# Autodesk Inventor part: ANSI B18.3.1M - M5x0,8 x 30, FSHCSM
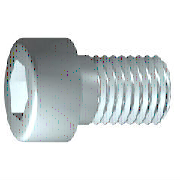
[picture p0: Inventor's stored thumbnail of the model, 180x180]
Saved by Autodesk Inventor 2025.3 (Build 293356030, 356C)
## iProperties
Created: 2024-01
Part Number: ANSI B18.3.1M - M5x0,8 x 30, FSHCSM
Material: Acciaio, Dolce
Description: Vite forgiata a testa incassata - Metrico
Document SubType Name: Modeling
Standard: ANSI B18.3.1M
Designer: R5800u
Standard Revision: 1979
Standards Organization: ANSI
Language: it-IT
Size Designation: M5x0,8 x 30
Categories: <MemberInstance><Categories><Category DisplayName="Elementi di fissaggio" InternalName="e4da775c-781d-43d5-af7c-5136215cf5a6" Mnemonic="FSTN"><Category DisplayN
Density: 7.85 g/cm^3
Appearance: Semilucidato
IsCustomPart: 0
Author: R5800u
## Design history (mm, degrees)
revolve "Corpo" stored, may be unused: angle "d10" = 90 deg
sketch "Schizzo2"
  geometry: L1 (0, -5.95)-(0, 5.95) reference; L2 (-5.95, 0)-(5.95, 0) reference; L3 (2.309, 0)-(1.155, -2); L4 (1.155, -2)-(-1.155, -2); L5 (-1.155, -2)-(-2.309, 0); L6 (-2.309, 0)-(-1.155, 2); L7 (-1.155, 2)-(1.155, 2); L8 (1.155, 2)-(2.309, 0); 2 further points
  constraints: 12 end point, 1 coincident, 1 horizontal alignment, 1 point on line, 12 other
extrude "Intaglio" join sketch "Schizzo2" stored distance "d11" = 10; taper "d12" = 0 deg
workplane "Work Plane1"
fillet "Fillet2" dims "d30" = 0.1 (= R)
body "Solid1"
fillet "Raccordo1" dims "d17" = 0.5 (= RR)
feature "Filettatura" dims "d13" = 29 (= GEL), "d14" = 0
chamfer "Smusso1" distance "d15" = 0.49076 (= -0.5 x SPD + 0.5 x GD); stored, may be unused: second distance "d16" = 0.49076 (= GUL), angle "d27" = 45 deg
sketch "Schizzo1"
  geometry: L1 (-1.167, 0)-(30, 0); L2 (30, 0)-(30, 2.5); L3 (30, 2.5)-(1, 2.5); L4 (1, 2.5)-(0.509, 2.5); L5 (0.509, 2.5)-(0, 2.5); L6 (0, 2.5)-(0, 4.25); L7 (0, 4.25)-(-5, 4.25); L8 (-5, 4.25)-(-5, 2.309); L9 (-5, 2.309)-(-2.5, 2.309); L10 (-2.5, 2.309)-(-1.167, 0); L11 (-12, 0)-(37, 0) reference; L12 (0, -0.85)-(0, 5.1) reference; L13 (1, 2.5)-(0, 2.5)
  constraints: 22 end point, 6 parallel, 2 collinear, 2 perpendicular, 1 horizontal, 1 point on line
  dimensions: "d1" = 29 distance from line of L3.end L2 (= GEL); "d2" = 0.49086 distance of L4.end L3.end (computed from GAL); "d3" = 5 distance between parallel lines of L8 L6 (= KOH); "d4" = 2.5 distance of L8.end L9.end (= INTI); "d5" = 60 deg angle of L10 L1; "d6" = 5 diameter of L3 L1 (= GD); "d7" = 5 diameter of L5 L1 (= BDM); "d8" = 4.6188 diameter of L9 L1 (= 1.1547 x SW); "d9" = 8.5 diameter of L7 L1 (= KOD); "d26" = 30 distance between parallel lines of L12 L2 (= NLG)
other parameters: "GD" = 5 (= NND) [user parameter; used in 2 equation terms], "NLG" = 30 [user parameter; used in 1 equation term], "GEL" = 29 [user parameter; used in 2 equation terms], "KOD" = 8.5 [user parameter; used in 1 equation term], "KOH" = 5 [user parameter; used in 1 equation term], "INTI" = 2.5 [user parameter; used in 1 equation term], "GAL" = 0.49076 (= 0.61345 x PTC) [user parameter; used in 1 equation term], "GUL" = 0.49076 (= 0.61345 x PTC) [user parameter; used in 1 equation term], "BDM" = 5 (= NND) [user parameter; used in 1 equation term], "SW" = 4 [user parameter; used in 2 equation terms], "RR" = 0.5 [user parameter; used in 1 equation term], "SPD" = 4.01848 [user parameter; used in 1 equation term], "d19" = 0, "d28" = 0, "d29" = 0, "R" = 0.1 [user parameter; used in 1 equation term], "TOA" = 30 deg [user parameter], "THREADDIA" = 5 [user parameter; used in 1 equation term], "TPU" = 12.5 (computed from PTC) [user parameter], "PTC" = 0.8 [user parameter; used in 4 equation terms], "NND" = 5 [user parameter; used in 2 equation terms], "E0" = 4.62 (= 1.155 x SW) [user parameter], "GD1" = 4.01848 (= THREADDIA - 1.2269 x PTC) [user parameter]
